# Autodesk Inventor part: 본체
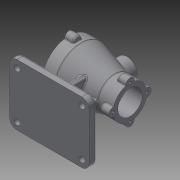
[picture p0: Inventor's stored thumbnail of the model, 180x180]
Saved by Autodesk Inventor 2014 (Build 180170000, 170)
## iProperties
Created: 2020-12
Part Number: 본체
Material: 알루미늄 6061
Document SubType Name: Modeling
Designer: kh
Density: 2.71 g/cm^3
Appearance: 기본값
Mass: 1034.39 g
Surface Area: 852.54 cm^2
Volume: 381.693 cm^3
Author: kh
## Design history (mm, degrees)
sketch "스케치1"
  geometry: L1 (-50, 0)-(50, 0); L2 (-50, 0)-(-50, 44); L3 (-50, 44)-(-30, 44); L4 (-30, 44)-(25, 27.5); L5 (25, 27.5)-(50, 27.5); L6 (50, 27.5)-(50, 0); 1 further point
  constraints: 12 end point, 2 perpendicular, 1 horizontal, 1 midpoint, 1 parallel, 1 vertical
  dimensions: "d0" = 100 distance of L1.start L1.end; "d1" = 50 distance of L1.end point (0, 0); "d2" = 88 diameter of L3 L1; "d3" = 55 diameter of L5 L1; "d4" = 20 distance of L2.end L3.end; "d6" = 25 distance of L4.end L5.end
revolve "회전1" sketch "스케치1" stored, may be unused: angle "d7" = 90 deg
node "작업 평면1"
sketch "스케치2"
  geometry: C1 r 17 at (0, 0); 1 further point
  constraints: 1 centre point, 1 coincident
  dimensions: "d9" = 34 diameter of C1
extrude "돌출1" join sketch "스케치2" stored distance "d10" = 10; taper "d11" = 0 deg
sketch "스케치3"
  geometry: C1 r 14 at (0, 0); 1 further point
  constraints: 1 centre point, 1 coincident
  dimensions: "d12" = 28 diameter of C1
extrude "돌출2" cut sketch "스케치3" distance "d13" = 1; taper "d14" = 0 deg
hole "구멍1" diameter "d17" = 22; stored, may be unused: countersink angle "d21" = 90 deg, drill point angle "d23" = 118 deg; dims "d15" = 10, "d16" = 10, "d18" = 6, "d19" = 4, "d20" = 2, "d22" = 45
chamfer "모따기1" distance "d24" = 1; stored, may be unused: second distance "d25" = 2, angle "d26" = 45 deg
sketch "스케치4"
  geometry: L1 (-50, -44)-(-50, 44) reference; L2 (-30, -44)-(-30, 44) reference; L3 (50, -27.5)-(50, 27.5) reference; L4 (-50, 0)-(50, 0); L5 (-50, 32)-(-27, 32); L6 (-27, 32)-(-27, 26); L7 (-27, 26)-(20, 26); L8 (20, 26)-(20, 20); L9 (20, 20)-(50, 20); 1 further point
  constraints: 12 end point, 3 parallel, 2 midpoint, 2 perpendicular, 2 point on line
  dimensions: "d27" = 64 diameter of L5 L4; "d28" = 23 distance between parallel lines of L1 L6; "d29" = 52 diameter of L7 L4; "d30" = 30 distance between parallel lines of L3 L8; "d31" = 40 diameter of L9 L4
  node "투영된 루프1"
node "작업 평면2"
sketch "스케치5"
  geometry: L1 (-65, 50)-(65, 50); L2 (65, 50)-(65, -50); L3 (65, -50)-(-65, -50); L4 (-65, -50)-(-65, 50); C1 r 11 at (0, 0) reference; 1 further point
  constraints: 8 end point, 2 parallel, 1 horizontal, 1 perpendicular
  dimensions: "d34" = 100 distance between parallel lines of L1 L3; "d35" = 130 distance between parallel lines of L4 L2; "d36" = 65 distance from line of L2 point (0, 0); "d37" = 50 distance from line of point (0, 0) L1
extrude "돌출3" join sketch "스케치5" distance "d38" = 12; taper "d39" = 0 deg
sketch "스케치6"
  geometry: L1 (-50, -44)-(-30, -44) reference; L2 (-30, -44)-(25, -27.5) reference; L3 (25, -27.5)-(50, -27.5) reference; L4 (65, -70)-(-65, -70) reference; L5 (-24, -40.112)-(-24, -70); L6 (24, -25.712)-(24, -70); L7 (-24, -40.112)-(24, -25.712); 1 further point
  constraints: 6 end point, 2 perpendicular, 2 point on line, 1 parallel
  dimensions: "d40" = 2 distance between parallel lines of L2 L7; "d41" = 48 distance between parallel lines of L6 L5; "d42" = 24 distance from line of point (0, 0) L5
extrude "돌출4" join sketch "스케치6" stored distance "d43" = 8; taper "d44" = 0 deg
sketch "스케치7"
  geometry: L1 (-70, -50)-(-70, 50) reference; L2 (-70, 25)-(-15, 25); L3 (-15, 25)-(-15, -25); L4 (-15, -25)-(-70, -25); 1 further point
  constraints: 6 end point, 2 perpendicular, 2 point on line, 1 parallel
  dimensions: "d45" = 50 distance between parallel lines of L2 L4; "d46" = 25 distance from line of point (0, 0) L2; "d47" = 55 distance between parallel lines of L1 L3
extrude "돌출5" join sketch "스케치7" stored distance "d48" = 8; taper "d49" = 0 deg
revolve "회전3" stored, may be unused: angle "d50" = 90 deg
sketch "스케치8"
  geometry: C1 r 7 at (0, 44); 2 further points
  constraints: 2 vertical alignment, 1 centre point, 1 other
  dimensions: "d51" = 14 diameter of C1
extrude "돌출6" join sketch "스케치8" distance "d52" = 15; taper "d53" = 0 deg
fillet "모깎기1" dims "d54" = 3
fillet "모깎기2" dims "d55" = 1
sketch "스케치9"
  geometry: C1 r 7 at (0, 27.5); 2 further points
  constraints: 2 vertical alignment, 1 centre point, 1 other
  dimensions: "d59" = 14 diameter of C1
extrude "돌출7" join sketch "스케치9" distance "d60" = 15; taper "d61" = 0 deg
fillet "모깎기3" dims "d62" = 3
fillet "모깎기4" dims "d63" = 1
hole "구멍2" diameter "d69" = 4.134; stored, may be unused: countersink angle "d73" = 90 deg, drill point angle "d75" = 118 deg; dims "d67" = 10, "d68" = 10, "d70" = 9, "d71" = 4, "d72" = 2, "d74" = 11
hole "구멍3" diameter "d81" = 4.134; stored, may be unused: countersink angle "d85" = 90 deg, drill point angle "d87" = 118 deg; dims "d79" = 10, "d80" = 10, "d82" = 9, "d83" = 4, "d84" = 2, "d86" = 11
fillet "모깎기5" dims "d91" = 3
fillet "모깎기8" dims "d94" = 1
fillet "모깎기9" dims "d95" = 12
hole "구멍4" diameter "d98" = 10; stored, may be unused: countersink angle "d102" = 90 deg, drill point angle "d104" = 118 deg; dims "d96" = 10, "d97" = 10, "d99" = 9, "d100" = 4, "d101" = 2, "d103" = 11
sketch "스케치10"
  geometry: L1 (7, 4)-(21, 4) reference; L2 (24, 1)-(24, -1) reference; L3 (21, -4)-(7, -4) reference; L4 (4, -7)-(4, -22) reference; L5 (1, -25)-(-1, -25) reference; L6 (-4, -22)-(-4, -7) reference; L7 (-7, -4)-(-21, -4) reference; L8 (-24, -1)-(-24, 1) reference; L9 (-21, 4)-(-7, 4) reference; L10 (-4, 7)-(-4, 22) reference; L11 (-1, 25)-(1, 25) reference; L12 (4, 22)-(4, 7) reference; L13 (-65, 38)-(-65, -38) reference; L14 (-53, -50)-(53, -50) reference; L15 (65, -38)-(65, 38) reference; L16 (53, 50)-(-53, 50) reference; L17 (20, 26)-(20, -26) reference; L18 (-27, 26)-(-27, -26) reference; C1 r 5 at (-53, 38) reference; C2 r 5 at (-53, -38) reference; C3 r 5 at (53, 38) reference; C4 r 5 at (53, -38) reference; A1 r 3 centre (7, 7) between (4, 7) and (7, 4) reference; A2 r 3 centre (21, 1) between (24, 1) and (21, 4) reference; A3 r 3 centre (21, -1) between (21, -4) and (24, -1) reference; A4 r 3 centre (7, -7) between (7, -4) and (4, -7) reference; A5 r 3 centre (1, -22) between (1, -25) and (4, -22) reference; A6 r 3 centre (-1, -22) between (-4, -22) and (-1, -25) reference; A7 r 3 centre (-7, -7) between (-4, -7) and (-7, -4) reference; A8 r 3 centre (-21, -1) between (-24, -1) and (-21, -4) reference; A9 r 3 centre (-21, 1) between (-21, 4) and (-24, 1) reference; A10 r 3 centre (-7, 7) between (-7, 4) and (-4, 7) reference; A11 r 3 centre (-1, 22) between (-1, 25) and (-4, 22) reference; A12 r 3 centre (1, 22) between (4, 22) and (1, 25) reference; A13 r 12 centre (-53, 38) between (-53, 50) and (-65, 38) reference; A14 r 12 centre (-53, -38) between (-65, -38) and (-53, -50) reference; A15 r 12 centre (53, -38) between (53, -50) and (65, -38) reference; A16 r 12 centre (53, 38) between (65, 38) and (53, 50) reference; 3 further points
  constraints: 1 vertical alignment, 2 other
  dimensions: "d109" = 10 distance from line of L14 point (0, -40)
feature "엠보싱1" sketch "스케치10" dims "d110" = 0.5, "d111" = 0
fillet "모깎기10" dims "d112" = 3
fillet "모깎기11" dims "d113" = 3
fillet "모깎기12" dims "d114" = 3
fillet "모깎기13" dims "d115" = 3
fillet "모깎기16" dims "d118" = 3
fillet "모깎기17" dims "d119" = 3
node "솔리드1"
pattern_circular "원형 패턴1" dims "d57" = 360 deg
pattern_circular "원형 패턴2" dims "d65" = 360 deg
pattern_circular "원형 패턴3" dims angle "d77" = 360 deg
pattern_circular "원형 패턴4" dims angle "d89" = 360 deg
pattern_linear "직사각형 패턴1"
node "투영된 루프2"
node "투영된 루프3"
other parameters: "d8" = 45, "d33" = -82
